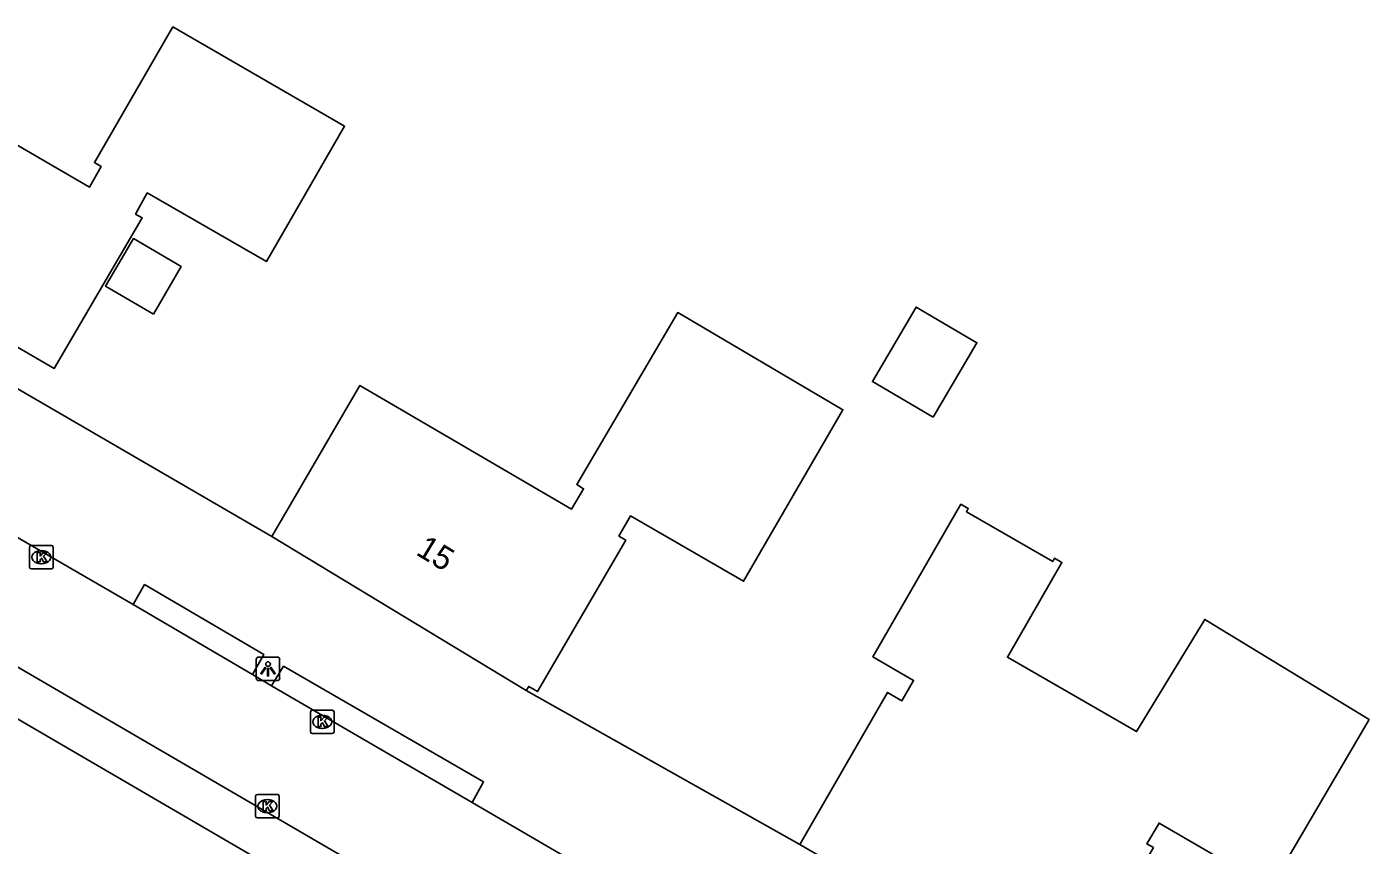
# Model space of a CAD drawing. Extents: x 156502 to 159074, y 384229 to 386094.
# Drawn here: x 157174.6 to 157231.9, y 385868.6 to 385903.5 of the extents above; entities that cross this region are included whole.
import ezdxf

# ---------------------------------------------------------------- set-up
doc = ezdxf.new("R2010")
doc.units = 0
for name, color, linetype in [('IMGEO_Hek', 7, 'Continuous'), ('IMGEO_Kolk', 7, 'Continuous'), ('IMGEO_Lichtpunt', 7, 'Continuous'), ('IMGEO_Pand', 7, 'Continuous'), ('IMGEO_Pand_nummerreeks', 7, 'Continuous'), ('IMGEO_Parkeervlak_open', 7, 'Continuous'), ('IMGEO_Rijbaan_lokaal_open', 7, 'Continuous'), ('IMGEO_Voetpad_open', 7, 'Continuous')]:
    doc.layers.add(name, color=color, linetype=linetype)

msp = doc.modelspace()

# ---------------------------------------------------------------- linework, layer by layer
at = {"layer": 'IMGEO_Hek'}
for points in [[(157167.911, 385891.794), (157185.093, 385881.809)], [(157195.952, 385875.233), (157207.627, 385868.664)]]:
    msp.add_lwpolyline(points, dxfattribs=at)
at = {"layer": 'IMGEO_Kolk'}
for p, q in [((157174.764, 385880.497), (157174.764, 385881.349)), ((157174.839, 385881.423), (157175.691, 385881.423)), ((157175.765, 385881.349), (157175.765, 385880.497)), ((157175.252, 385881.203), (157175.277, 385881.203)), ((157175.691, 385880.423), (157174.839, 385880.423)), ((157175.275, 385880.643), (157175.25, 385880.643)), ((157186.751, 385873.47), (157186.751, 385874.322)), ((157186.826, 385874.396), (157187.678, 385874.396)), ((157187.239, 385874.176), (157187.264, 385874.176)), ((157187.752, 385874.322), (157187.752, 385873.47)), ((157187.678, 385873.396), (157186.826, 385873.396)), ((157187.262, 385873.616), (157187.237, 385873.616)), ((157184.407, 385869.875), (157184.407, 385870.727)), ((157184.482, 385870.801), (157185.334, 385870.801)), ((157184.895, 385870.581), (157184.92, 385870.581)), ((157185.408, 385870.727), (157185.408, 385869.875)), ((157184.918, 385870.021), (157184.893, 385870.021)), ((157185.334, 385869.801), (157184.482, 385869.801))]:
    msp.add_line(p, q, dxfattribs=at)
for points in [[(157174.764, 385880.497), (157174.764, 385881.349)], [(157174.839, 385881.423), (157175.691, 385881.423)], [(157175.765, 385881.349), (157175.765, 385880.497)], [(157175.085, 385881.123), (157175.208, 385881.123), (157175.208, 385880.972), (157175.338, 385881.123), (157175.502, 385881.123), (157175.356, 385880.972), (157175.509, 385880.723), (157175.357, 385880.723), (157175.272, 385880.887), (157175.208, 385880.82), (157175.208, 385880.723), (157175.085, 385880.723), (157175.085, 385881.123)], [(157175.691, 385880.423), (157174.839, 385880.423)], [(157186.751, 385873.47), (157186.751, 385874.322)], [(157186.826, 385874.396), (157187.678, 385874.396)], [(157187.072, 385874.096), (157187.195, 385874.096), (157187.195, 385873.945), (157187.325, 385874.096), (157187.489, 385874.096), (157187.343, 385873.945), (157187.496, 385873.696), (157187.344, 385873.696), (157187.259, 385873.86), (157187.195, 385873.793), (157187.195, 385873.696), (157187.072, 385873.696), (157187.072, 385874.096)], [(157187.752, 385874.322), (157187.752, 385873.47)], [(157187.678, 385873.396), (157186.826, 385873.396)], [(157184.407, 385869.875), (157184.407, 385870.727)], [(157184.482, 385870.801), (157185.334, 385870.801)], [(157184.728, 385870.501), (157184.851, 385870.501), (157184.851, 385870.35), (157184.981, 385870.501), (157185.145, 385870.501), (157184.999, 385870.35), (157185.152, 385870.101), (157185, 385870.101), (157184.915, 385870.265), (157184.851, 385870.198), (157184.851, 385870.101), (157184.728, 385870.101), (157184.728, 385870.501)], [(157185.408, 385870.727), (157185.408, 385869.875)], [(157185.334, 385869.801), (157184.482, 385869.801)]]:
    msp.add_lwpolyline(points, dxfattribs=at)
for centre, start, end in [((157174.841, 385881.347), 91.552, 178.448), ((157174.841, 385881.347), 91.552, 178.448), ((157175.689, 385881.347), 1.552, 88.448), ((157175.689, 385881.347), 1.552, 88.448), ((157174.841, 385880.499), 181.552, 268.448), ((157174.841, 385880.499), 181.552, 268.448), ((157175.689, 385880.499), 271.552, 358.448), ((157175.689, 385880.499), 271.552, 358.448), ((157186.828, 385874.32), 91.552, 178.448), ((157186.828, 385874.32), 91.552, 178.448), ((157187.676, 385874.32), 1.552, 88.448), ((157187.676, 385874.32), 1.552, 88.448), ((157186.828, 385873.472), 181.552, 268.448), ((157186.828, 385873.472), 181.552, 268.448), ((157187.676, 385873.472), 271.552, 358.448), ((157187.676, 385873.472), 271.552, 358.448), ((157184.484, 385870.725), 91.552, 178.448), ((157184.484, 385870.725), 91.552, 178.448), ((157185.332, 385870.725), 1.552, 88.448), ((157185.332, 385870.725), 1.552, 88.448), ((157184.484, 385869.877), 181.552, 268.448), ((157184.484, 385869.877), 181.552, 268.448), ((157185.332, 385869.877), 271.552, 358.448), ((157185.332, 385869.877), 271.552, 358.448)]:
    msp.add_arc(centre, 0.0765, start, end, dxfattribs=at)
for centre, major_axis, ratio, start_param, end_param in [((157175.251, 385880.923), (-0.387, 0.002), 0.722429, 4.712389, 7.853982), ((157175.276, 385880.923), (-0.39, 0.002), 0.717154, 1.570796, 4.712389), ((157187.238, 385873.896), (-0.387, 0.002), 0.722429, 4.712389, 7.853982), ((157187.263, 385873.896), (-0.39, 0.002), 0.717154, 1.570796, 4.712389), ((157184.894, 385870.301), (-0.387, 0.002), 0.722429, 4.712389, 7.853982), ((157184.919, 385870.301), (-0.39, 0.002), 0.717154, 1.570796, 4.712389)]:
    msp.add_ellipse(centre, major_axis=major_axis, ratio=ratio, start_param=start_param, end_param=end_param, dxfattribs=at)
at = {"layer": 'IMGEO_Lichtpunt'}
for p, q in [((157184.436, 385876.563), (157184.436, 385875.756)), ((157184.436, 385876.563), (157184.436, 385875.756)), ((157185.338, 385876.658), (157184.53, 385876.658)), ((157185.338, 385876.658), (157184.53, 385876.658)), ((157185.432, 385875.756), (157185.432, 385876.563)), ((157185.432, 385875.756), (157185.432, 385876.563)), ((157184.53, 385875.662), (157185.338, 385875.662)), ((157184.53, 385875.662), (157185.338, 385875.662))]:
    msp.add_line(p, q, dxfattribs=at)
for points in [[(157184.81, 385876.227), (157184.849, 385876.199), (157184.661, 385875.937), (157184.623, 385875.964), (157184.81, 385876.227)], [(157184.912, 385876.179), (157184.959, 385876.179), (157184.959, 385875.857), (157184.912, 385875.857), (157184.912, 385876.179)], [(157185.022, 385876.199), (157185.06, 385876.226), (157185.247, 385875.964), (157185.208, 385875.936), (157185.022, 385876.199)]]:
    msp.add_lwpolyline(points, dxfattribs=at)
msp.add_circle((157184.935, 385876.361), 0.0994, dxfattribs=at)
for centre, start, end in [((157184.53, 385876.563), 90, 180), ((157184.53, 385876.563), 90, 180), ((157185.338, 385876.563), 0, 90), ((157185.338, 385876.563), 0, 90), ((157184.53, 385875.756), 180, 270), ((157184.53, 385875.756), 180, 270), ((157185.338, 385875.756), 270, 0), ((157185.338, 385875.756), 270, 360)]:
    msp.add_arc(centre, 0.0946, start, end, dxfattribs=at)
at = {"layer": 'IMGEO_Pand'}
for points in [[(157163.686, 385894.272), (157168.192, 385902.015), (157177.313, 385896.706), (157177.822, 385897.585), (157177.527, 385897.755), (157180.877, 385903.546), (157188.204, 385899.308), (157184.874, 385893.54), (157179.785, 385896.459), (157179.286, 385895.561), (157179.562, 385895.399), (157175.806, 385888.97), (157168.68, 385893.106), (157167.911, 385891.794)], [(157180.048, 385891.283), (157178.006, 385892.477), (157179.194, 385894.511), (157181.237, 385893.318), (157180.048, 385891.283)], [(157185.093, 385881.809), (157188.853, 385888.249), (157197.887, 385882.973), (157198.399, 385883.845), (157198.106, 385884.017), (157202.417, 385891.356), (157209.465, 385887.215), (157205.225, 385879.893), (157200.407, 385882.684), (157199.904, 385881.82), (157200.198, 385881.649), (157196.439, 385875.192), (157196.06, 385875.413), (157195.952, 385875.233)], [(157213.318, 385886.894), (157210.726, 385888.416), (157212.591, 385891.591), (157215.183, 385890.069), (157213.318, 385886.894)], [(157207.627, 385868.664), (157211.365, 385875.15), (157211.978, 385874.797), (157212.478, 385875.666), (157210.745, 385876.665), (157214.5, 385883.18), (157214.812, 385883), (157214.732, 385882.862), (157218.418, 385880.738), (157218.498, 385880.877), (157218.81, 385880.697), (157216.482, 385876.657), (157221.993, 385873.482), (157224.899, 385878.267), (157231.916, 385874.005), (157227.702, 385866.82), (157222.95, 385869.578), (157222.433, 385868.694), (157222.709, 385868.533), (157218.954, 385862.085)], [(157195.952, 385875.233), (157185.093, 385881.809)], [(157207.627, 385868.664), (157218.954, 385862.085)]]:
    msp.add_lwpolyline(points, dxfattribs=at)
at = {"layer": 'IMGEO_Parkeervlak_open'}
msp.add_lwpolyline([(157138.908, 385894.614), (157192.564, 385863.354)], dxfattribs=at)
at = {"layer": 'IMGEO_Rijbaan_lokaal_open'}
for points in [[(157139.856, 385896.261), (157193.373, 385865.1)], [(157172.275, 385882.9), (157179.189, 385878.901)], [(157184.271, 385875.92), (157179.189, 385878.901)], [(157184.271, 385875.92), (157185.088, 385875.436)], [(157193.644, 385870.453), (157185.088, 385875.436)], [(157193.644, 385870.453), (157201.692, 385865.761)]]:
    msp.add_lwpolyline(points, dxfattribs=at)
at = {"layer": 'IMGEO_Voetpad_open'}
for points in [[(157167.911, 385891.794), (157185.093, 385881.809)], [(157179.189, 385878.901), (157179.666, 385879.755), (157184.758, 385876.767), (157184.271, 385875.92)], [(157185.088, 385875.436), (157185.6, 385876.273), (157194.131, 385871.332), (157193.644, 385870.453)], [(157195.952, 385875.233), (157207.627, 385868.664)]]:
    msp.add_lwpolyline(points, dxfattribs=at)

# ---------------------------------------------------------------- texts
at = {"layer": 'IMGEO_Pand_nummerreeks'}
msp.add_text('15', height=1, rotation=328.8006, dxfattribs=at).set_placement((157191.201, 385881.056))

doc.saveas('drawing.dxf')
